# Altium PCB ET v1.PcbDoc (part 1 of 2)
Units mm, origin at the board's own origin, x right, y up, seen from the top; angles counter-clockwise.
Board outline 210 x 190 mm, 4 copper layers (Top Layer, GND, PWR, Bottom Layer), stack 0.538 mm thick; 137 components, 80 nets, 364 pads, 677 vias.
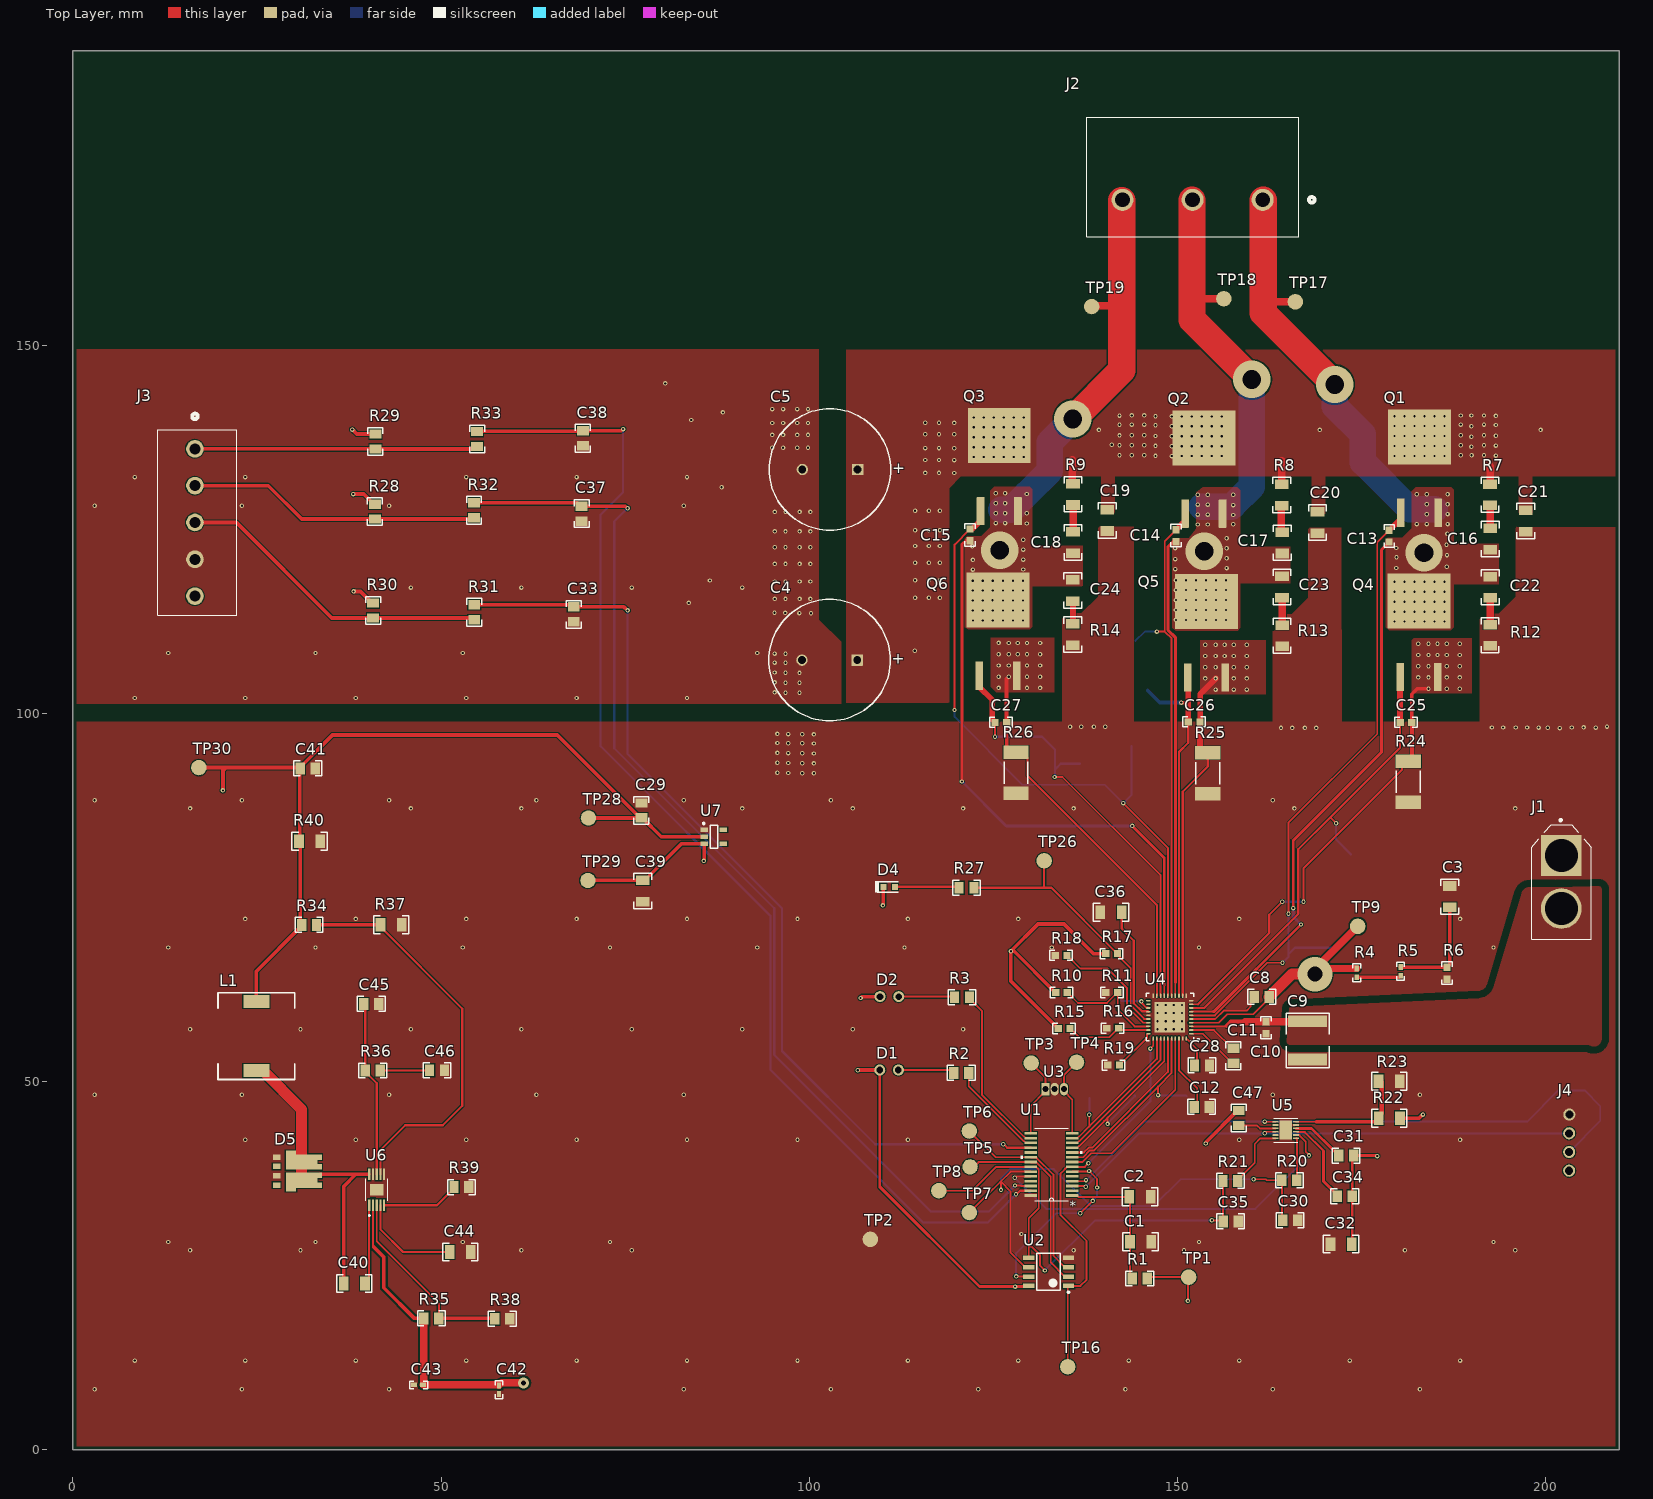
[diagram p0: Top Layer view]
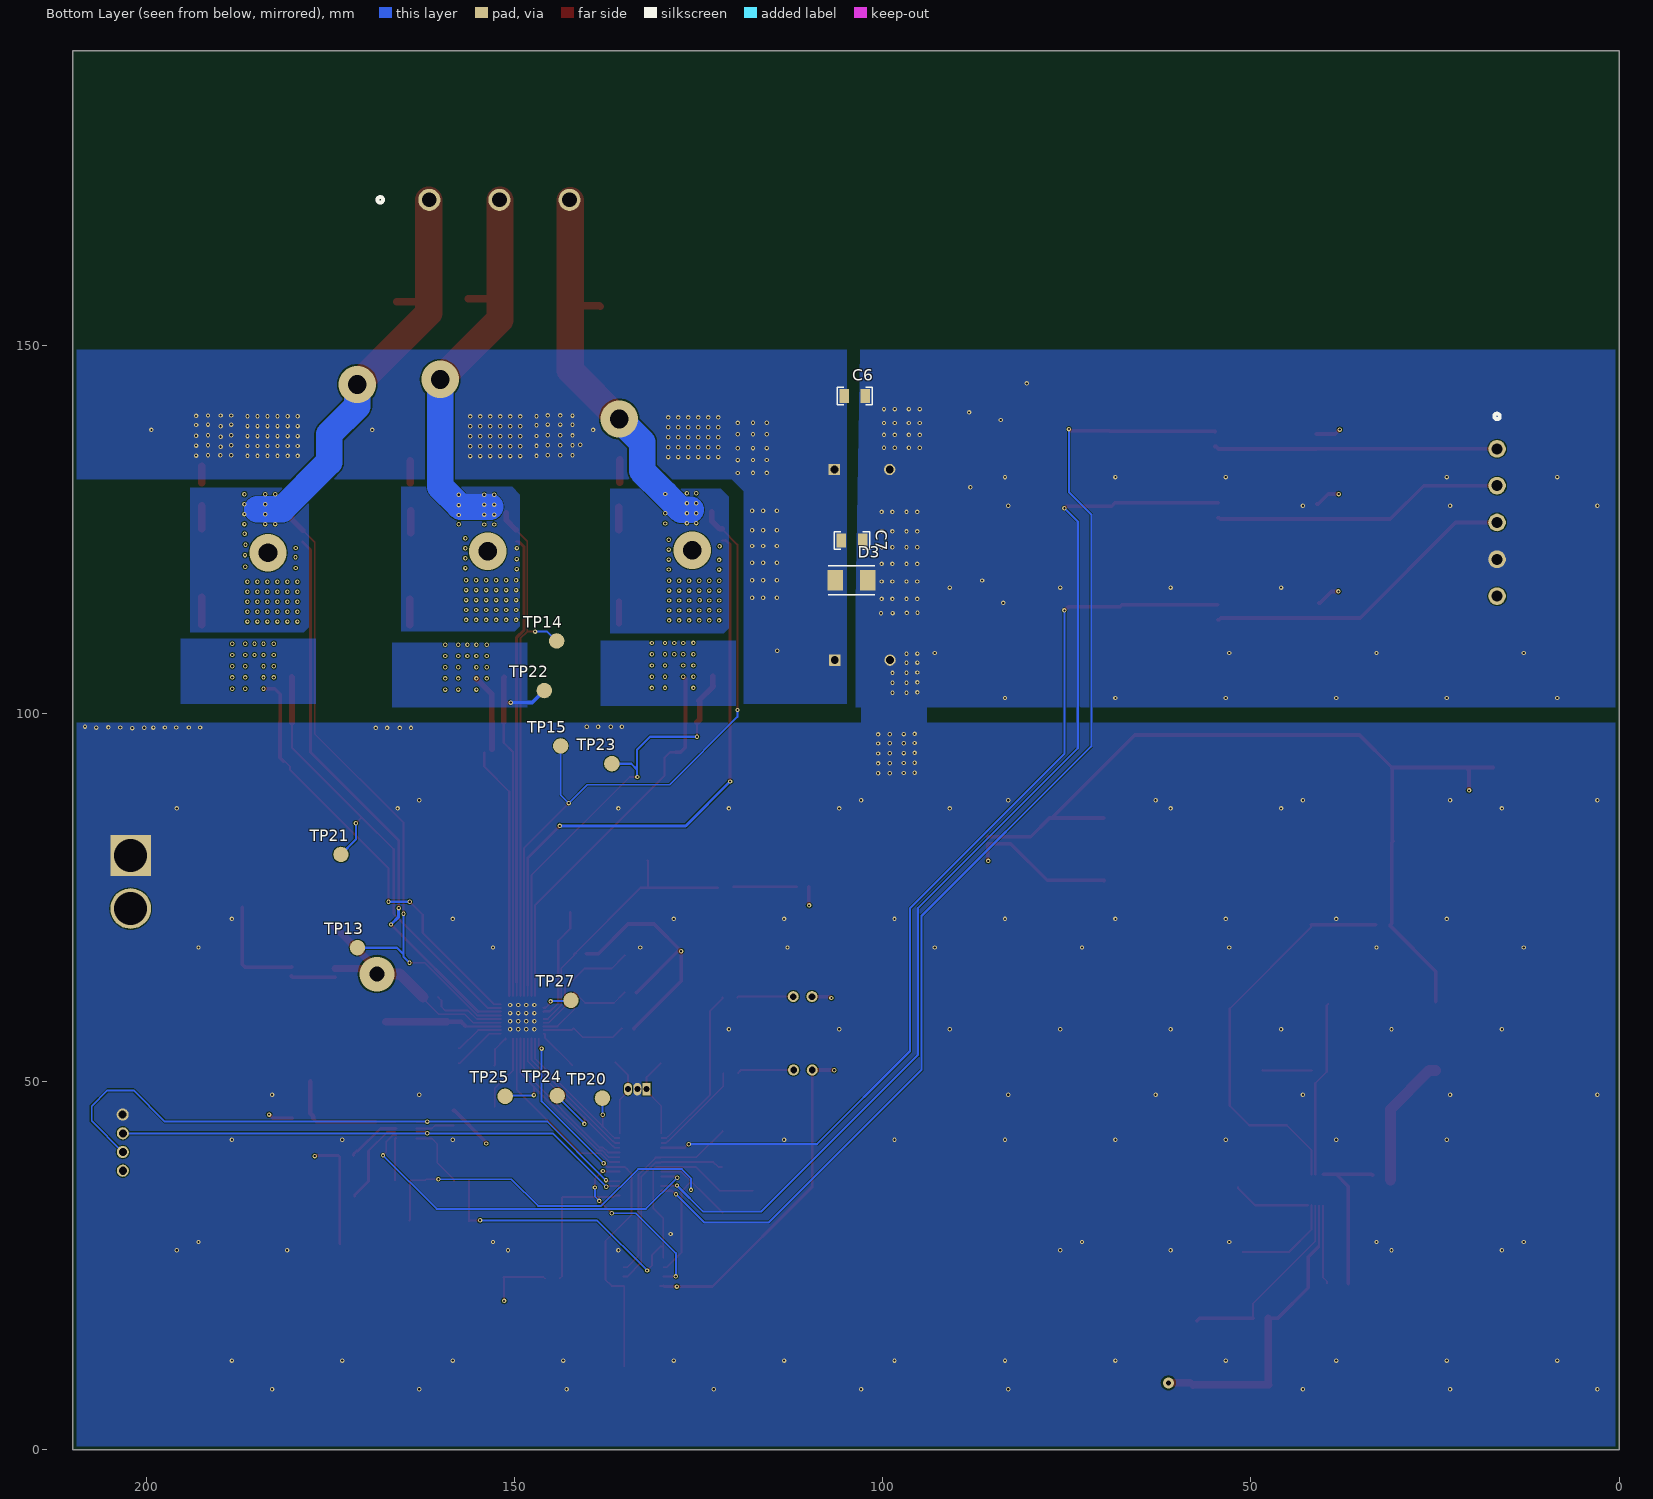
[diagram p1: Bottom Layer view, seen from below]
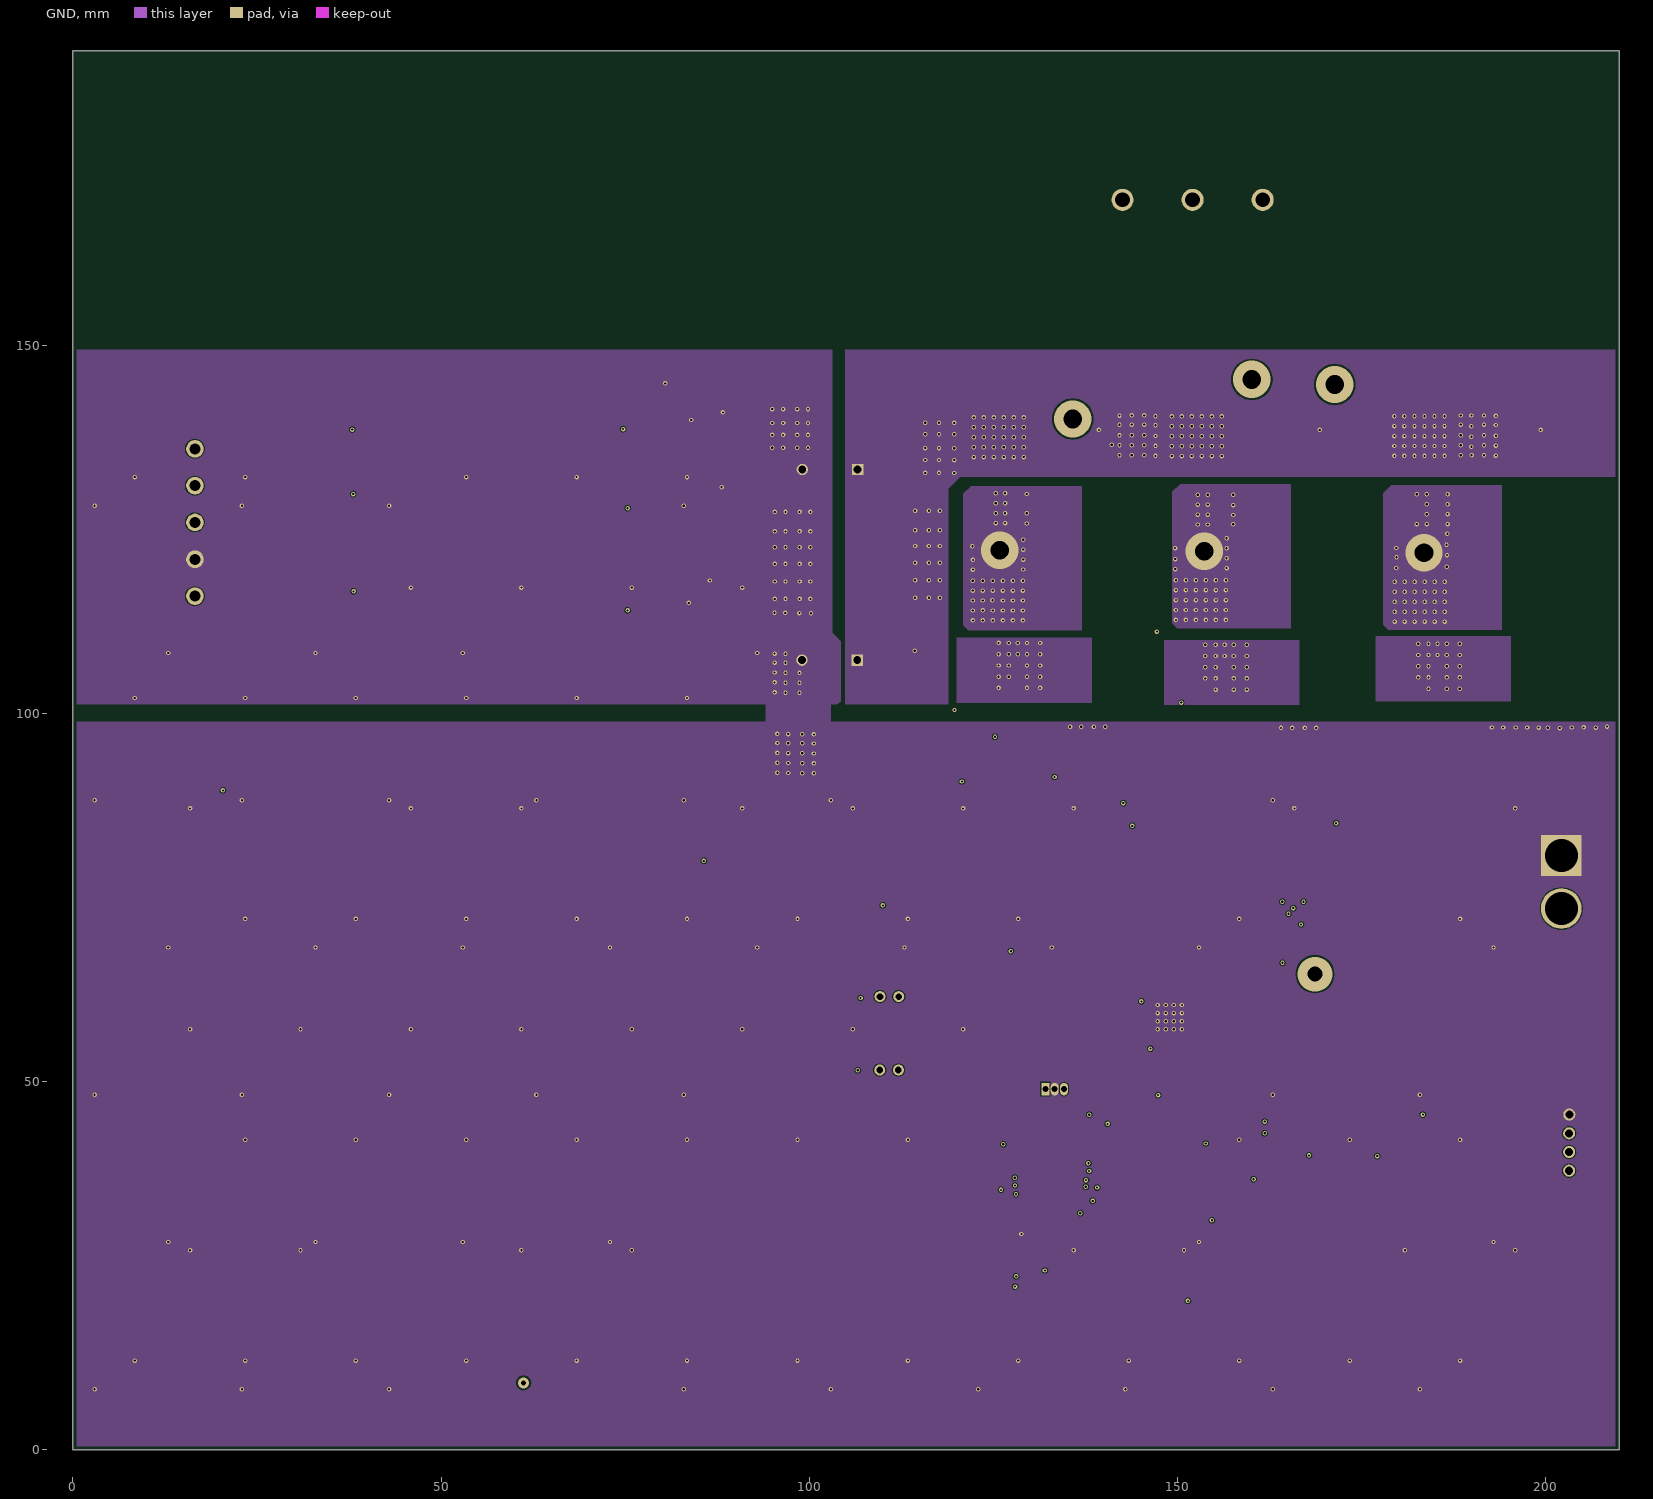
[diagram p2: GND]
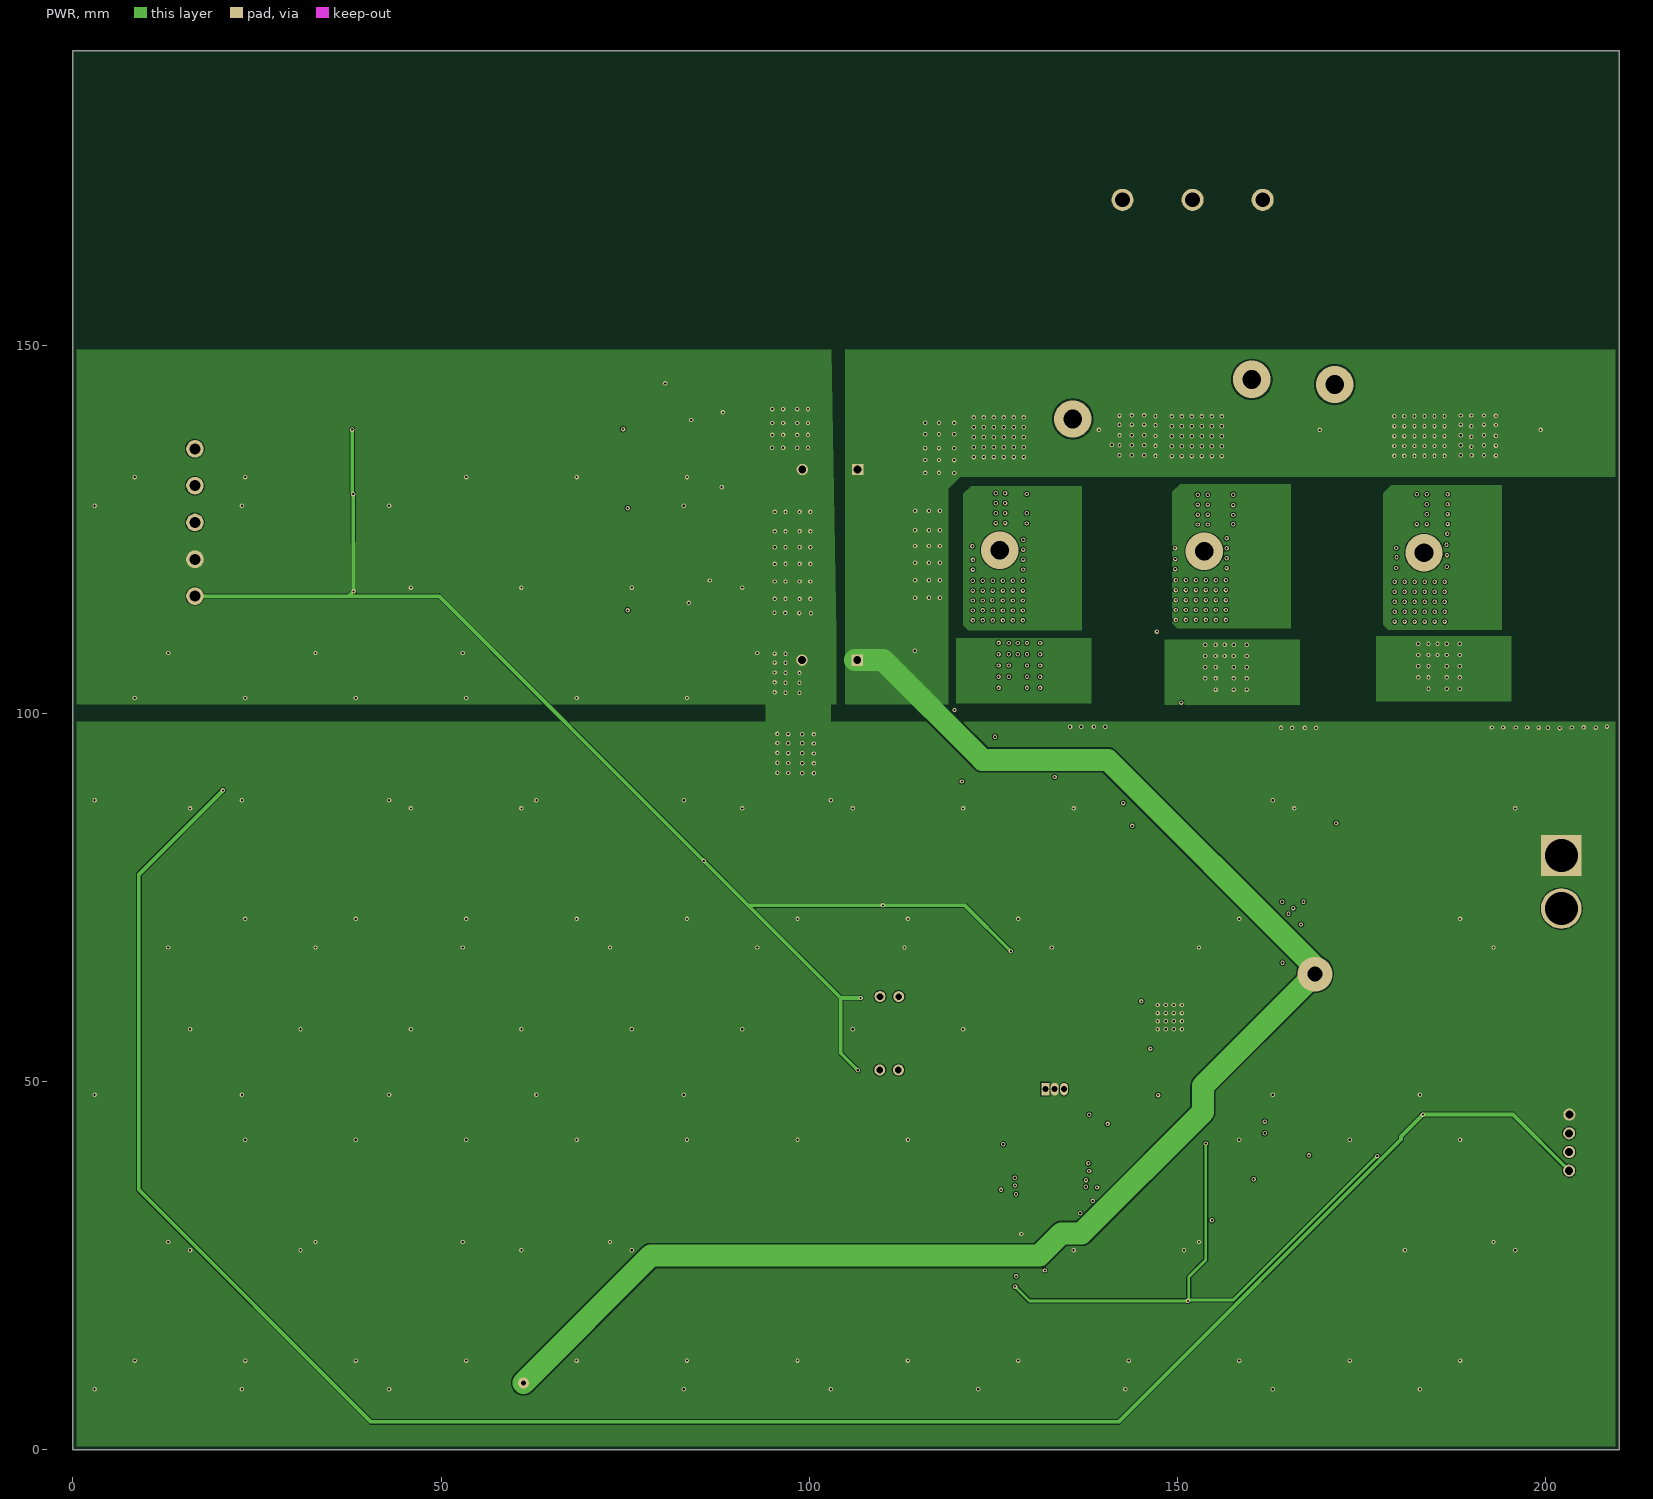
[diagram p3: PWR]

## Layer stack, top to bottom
Top Solder: solder mask 0.0102, Solder Resist, Dk 3.5
Top Layer: signal copper 0.0356
Dielectric 1: prepreg 0.0965, PP-012, Dk 4
GND: signal copper 0.0356
Dielectric3: core 0.2032, Core-024, Dk 4.6
PWR: signal copper 0.0356
Dielectric2: prepreg 0.0965, PP-012, Dk 4
Bottom Layer: signal copper 0.0356
Bottom Solder: solder mask 0.0102, Solder Resist, Dk 3.5

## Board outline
0,0 0,190 210,190 210,0

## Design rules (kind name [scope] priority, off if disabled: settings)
BoardOutlineClearance [All] p1: gap=0.5 ignorepadtopadclearanceinfootprint=FALSE
Clearance [//InNamedPolygon('Top_NetC13_1') &&  InNamedPolygon('NONET_L-01_P-001')] p1: gap=1 ignorepadtopadclearanceinfootprint=TRUE
Clearance "Board outline" [All vs InNet('VDC')] p2: gap=0.254 ignorepadtopadclearanceinfootprint=TRUE
Clearance Default [All] p3: gap=0.127 ignorepadtopadclearanceinfootprint=TRUE
ComponentClearance ComponentClearance_RS1 [InComponent('RS1') vs InComponent('L2')] p1: gap=0 collisioncheckmode=3 verticalgap=0 showdistances=FALSE
ComponentClearance ComponentClearance_J6 [InComponent('J6') vs InComponent('L4')] p2: gap=0 collisioncheckmode=3 verticalgap=0 showdistances=FALSE
ComponentClearance [All] p3: gap=0.25 collisioncheckmode=3 verticalgap=2540 showdistances=FALSE
DiffPairsRouting [InDifferentialPairClass('All Differential Pairs')] p1: maxlimit=0.254 minlimit=0.127 mostfreqgap=0.254 toplayer_maxgap=0.25 toplayer_prefgap=0.243 toplayer_minwidth=0.075 toplayer_maxwidth=0.25 toplayer_prefwidth=0.25 midlayer1_minwidth=0.381 midlayer1_maxwidth=0.381 midlayer1_prefwidth=0.381 midlayer2_minwidth=0.381 midlayer2_maxwidth=0.381 midlayer2_prefwidth=0.381 bottomlayer_maxgap=0.25 bottomlayer_prefgap=0.243 bottomlayer_minwidth=0.075 bottomlayer_maxwidth=0.25 bottomlayer_prefwidth=0.25 impedanceprofiledriven=TRUE maxuncoupledlength=12.7
Height [All] p1: minheight=0 maxheight=100 prefheight=12.7
HoleSize [All] p1: absolutevalues=TRUE maxlimit=10 minlimit=0.254 maxpercent=80.000 minpercent=20.000
HoleToHoleClearance [All] p1: gap=0.1 allowstackedmicrovias=TRUE
MatchedLengths [All] p1: tolerance=1 checknetsindiffpair=TRUE checkdiffpairvsdiffpair=FALSE checkxsignals=FALSE checkothers=FALSE
MinimumSolderMaskSliver [All] p1: minsoldermaskwidth=0.1
PasteMaskExpansion [All] p1: expansion=-0.1
PlaneClearance [All] p1: clearance=0.5
PolygonConnect [All] p1: connectstyle=Direct reliefconductorwidth=0.254 reliefentries=4 polygonreliefangle="90 Angle" airgapwidth=0.254
RoutingVias [All] p1: holewidth=0.254 width=0.508 viastyle="Through Hole" minholewidth=0.254 minwidth=0.508 maxholewidth=0.5 maxwidth=1
SilkToSilkClearance [All] p1 off: silktosilkclearance=0.254
SilkToSolderMaskClearance [IsPad] p1 off: minsilkscreentomaskgap=0.254 clearancetoexposedcopper=TRUE
SolderMaskExpansion [All] p1: expansion=0.05 istentingtop=FALSE
Width [All] p1: maxlimit=6.8 minlimit=0.127 preferedwidth=0.2 minimp=50.000000 maximp=50.000000 favimp=50.000000
20 further rules are at their usual default settings.

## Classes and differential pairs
component class "ETMicrocontroller Schematic": C1 C2 C30 C31 C32 C34 C35 C47 D1 D2 J4 R1 R2 R3 R20 R21 R22 R23 TP1 TP2 TP3 TP4 TP5 TP6 TP7 TP8 U1 U2 U3 U5
component class ET_SchDoc: C3 C4 C5 C6 C7 C8 C9 C10 C11 C12 C13 C14 C15 C16 C17 C18 C19 C20 C21 C22 C23 C24 C25 C26 C27 C28 C29 C33 C36 C37 C38 C39 C40 C41 C42 C43 C44 C45 C46 D3 D4 D5 "f x" J1 J2 J3 L1 Q1 Q2 Q3 Q4 Q5 Q6 R4 R5 R6 R7 R8 R9 R10 R11 R12 R13 R14 R15 R16 R17 R18 R19 R24 R25 R26 R27 R28 R29 R30 R31 R32 R33 R34 R35 R36 R37 R38 R39 R40 TP9 TP13 TP14 TP15 TP16 TP17 TP18 TP19 TP20 TP21 TP22 TP23 TP24 TP25 TP26 TP27 TP28 TP29 TP30 U4 U6 U7

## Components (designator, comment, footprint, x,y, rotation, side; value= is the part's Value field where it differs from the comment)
C1 "10uF" 1206 145.02,28.258 r0 top
C2 "0.1uF" 1206 144.942,34.362 r0 top
C3 "0.1uF" 1206 186.994,75.129 r270 top
C4 "390uF" YXJ_1600x2500 102.766,107.261 r180 top
C5 "390uF" YXJ_1600x2500 102.824,133.152 r180 top
C6 "2.2uF" 1206 103.814,143.137 r0 bottom
C7 "0.1uF" 1206 104.203,123.499 r0 bottom
C8 "1uF" 0805_HV 161.465,61.517 r180 top
C9 "10uF" 2220_280 167.71,55.6 r90 top
C10 "0.1uF" 0603 162.042,57.328 r90 top
C11 "0.047uF" 0805_HV 157.62,53.519 r90 top
C12 "1uF" 0805_HV 153.305,46.577 r180 top
C13 "1nF" 0603 178.779,124.093 r90 top
C14 "1nF" 0603 149.815,124.156 r90 top
C15 "1nF" 0603 121.837,124.26 r90 top
C16 "3900pF" 1206 192.494,123.694 r90 top
C17 "3900pF" 1206 164.236,123.191 r90 top
C18 "3900pF" 1206 135.834,123.242 r90 top
C19 "2.2uF" 1206 140.499,126.244 r90 top
C20 "2.2uF" 1206 169.035,125.949 r90 top
C21 "2.2uF" 1206 197.306,126.149 r90 top
C22 "3900pF" 1206 192.518,117.152 r90 top
C23 "3900pF" 1206 164.217,117.187 r90 top
C24 "3900pF" 1206 135.811,116.718 r90 top
C25 "1nF" 0603 181.064,98.809 r180 top
C26 "1nF" 0603 152.287,98.87 r0 top
C27 "1nF" 0603 126.033,98.801 r180 top
C28 "1uF" 0805_HV 153.348,52.211 r180 top
C29 "1uF" 0805_HV 77.207,86.843 r90 top
C30 "47pF" 0805_HV 165.322,31.167 r180 top
C31 "0.1uF" 0805_HV 172.932,39.968 r180 top
C32 "10uF" 1206 172.254,27.945 r0 top
C33 "1000pF" 0805_HV 68.008,113.473 r270 top
C34 "0.1uF" 0805_HV 172.742,34.438 r180 top
C35 "47pF" 0805_HV 157.238,31.014 r180 top
C36 "0.1uF" 1206 140.999,73.005 r0 top
C37 "1000pF" 0805_HV 69.087,127.158 r270 top
C38 "1000pF" 0805_HV 69.271,137.393 r270 top
C39 "2.2uF" 1206 77.404,75.906 r90 top
C40 "0.1uF" 1206 38.22,22.591 r180 top
C41 "47uF" 0805_HV 31.901,92.552 r180 top
C42 "2.2uF" 0402 57.87,8.157 r90 top
C43 "2.2uF" 0402 46.946,8.82 r0 top
C44 "0.1uF" 1206 52.609,26.869 r180 top
C45 "15pF" 0805_HV 40.519,60.565 r180 top
C46 "3300pF" 0805_HV 49.451,51.547 r180 top
C47 "0.1uF" 0805_HV 158.332,45.062 r90 top
D1 "LED" LED_TH 110.851,51.585 r0 top
D2 "LED" LED_TH 110.892,61.556 r0 top
D3 "SMBJ70CA-13-F" SMB-Bi 104.251,118.1 r0 bottom
D4 "RED" WL-SMCW_GREEN 110.871,76.463 r0 top
D5 "V8KM60DUHM3/H" V8KM60DUHM3/H 28.537,37.86 r270 top
J1 "XT60 PRT-10474" "XT60 PRT-10474" 202.16,77.116 r270 top
J2 "MotorPhase 1904150" "MotorPhase 1904150" 161.593,169.78 r180 top
J3 "MotorHall_1792892" MotorHall_1792892 16.571,135.953 r270 top
J4 "USB Header" "USB Header" 203.233,41.718 r90 top
L1 "27uH" MSS1038T-273MLC 24.917,56.197 r180 top
Q1 "CSD19536KTT" KTT0002A 182.886,134.169 r90 top
Q2 "CSD19536KTT" KTT0002A 153.601,134.045 r90 top
Q3 "CSD19536KTT" KTT0002A 125.814,134.388 r90 top
Q4 "CSD19536KTT" KTT0002A 182.824,111.885 r90 top
Q5 "CSD19536KTT" KTT0002A 153.967,111.813 r90 top
Q6 "CSD19536KTT" KTT0002A 125.65,112.04 r90 top
R1 "330" 0805_HV 144.89,23.271 r0 top
R2 "330" 0805_HV 120.657,51.198 r180 top
R3 "330" 0805_HV 120.754,61.468 r180 top
R4 "2.00M" 0402 174.381,64.779 r90 top
R5 "2.00M" 0402 180.32,64.988 r270 top
R6 "191k" 0603 186.635,64.737 r90 top
R7 "1.50" 1206 192.471,129.724 r90 top
R8 "1.50" 1206 164.185,129.688 r90 top
R9 "1.50" 1206 135.833,129.778 r90 top
R10 "75k" 0603 134.27,62.105 r180 top
R11 "75k" 0603 141.101,62.121 r0 top
R12 "1.50" 1206 192.482,110.632 r90 top
R13 "1.50" 1206 164.228,110.573 r90 top
R14 "1.50" 1206 135.813,110.725 r90 top
R15 "75k" 0603 134.623,57.229 r180 top
R16 "75k" 0603 141.224,57.258 r0 top
R17 "10k" 0603 141.082,67.391 r0 top
R18 "47k" 0603 134.209,67.164 r180 top
R19 "47k" 0603 141.34,52.234 r0 top
R20 "22" 0805_HV 165.222,36.606 r180 top
R21 "22" 0805_HV 157.214,36.523 r180 top
R22 "4.7k" 1206 178.795,45.039 r180 top
R23 "10k" 1206 178.776,50.074 r180 top
R24 "10m" 2512 181.391,90.738 r90 top
R25 "10m" 2512 154.143,91.899 r90 top
R26 "10m" 2512 128.087,91.964 r90 top
R27 "1k" 0805_HV 121.364,76.349 r0 top
R28 "3.3k" 0805_HV 41.022,127.436 r90 top
R29 "3.3k" 0805_HV 41.086,136.958 r90 top
R30 "3.3k" 0805_HV 40.774,114.005 r90 top
R31 "100" 0805_HV 54.515,113.77 r90 top
R32 "100" 0805_HV 54.473,127.603 r90 top
R33 "100" 0805_HV 54.884,137.286 r90 top
R34 "53.6k" 0805_HV 32.073,71.297 r180 top
R35 "113k" 0805_HV 48.68,17.852 r180 top
R36 "88.7k" 0805_HV 40.722,51.521 r180 top
R37 "10k" 1206 43.225,71.303 r180 top
R38 "5.49k" 0805_HV 58.312,17.796 r180 top
R39 "154k" 0805_HV 52.767,35.691 r180 top
R40 "10k" 1206 32.151,82.663 r180 top
TP1 "Test Point 1" TP200_SMD 151.539,23.453 r180 top
TP2 "Test Point 1" TP200_SMD 108.303,28.594 r90 top
TP3 "Test Point 1" TP200_SMD 130.156,52.531 r270 top
TP4 "Test Point 1" TP200_SMD 136.311,52.643 r270 top
TP5 "Test Point 1" TP200_SMD 121.849,38.424 r270 top
TP6 "Test Point 1" TP200_SMD 121.757,43.299 r270 top
TP7 "Test Point 1" TP200_SMD 121.75,32.222 r180 top
TP8 "Test Point 1" TP200_SMD 117.618,35.192 r180 top
TP9 "Test Point 1" TP200_SMD 174.503,71.105 r0 top
TP13 "Test Point 1" TP200_SMD 171.357,68.202 r90 bottom
TP14 "Test Point 1" TP200_SMD 144.301,109.862 r90 bottom
TP15 "Test Point 1" TP200_SMD 143.753,95.602 r90 bottom
TP16 "Test Point 1" TP200_SMD 135.118,11.28 r90 top
TP17 "Test Point 1" TP200_SMD 166.022,155.929 r270 top
TP18 "Test Point 1" TP200_SMD 156.312,156.34 r270 top
TP19 "Test Point 1" TP200_SMD 138.363,155.28 r270 top
TP20 "Test Point 1" TP200_SMD 138.083,47.769 r90 bottom
TP21 "Test Point 1" TP200_SMD 173.596,80.861 r90 bottom
TP22 "Test Point 1" TP200_SMD 145.97,103.128 r90 bottom
TP23 "Test Point 1" TP200_SMD 136.801,93.195 r90 bottom
TP24 "Test Point 1" TP200_SMD 144.218,48.095 r90 bottom
TP25 "Test Point 1" TP200_SMD 151.3,48.015 r90 bottom
TP26 "Test Point 1" TP200_SMD 131.914,80.007 r90 top
TP27 "Test Point 1" TP200_SMD 142.359,61.044 r90 bottom
TP28 "Test Point 1" TP200_SMD 70.022,85.813 r90 top
TP29 "Test Point 1" TP200_SMD 69.949,77.329 r90 top
TP30 "Test Point 1" TP200_SMD 17.11,92.665 r180 top
U1 "MSP430G2553IPW28" MSP430G2353IPW28 132.914,38.761 r180 top
U2 "MCP3202T-CI/SN" MCP3202T-CI/SN 132.518,24.164 r180 top
U3 "DRV5011" Hall_sensor 133.343,48.991 r0 top
U4 "DRV8353FHRTAR" DRV8353FHRTAR 148.975,58.763 r180 top
U5 "FT234XD-R" FT234XD-R 164.733,43.431 r180 top
U6 "TPS54160DGQ" TPS54160DGQ 41.258,35.317 r90 top
U7 "TPS709B345DBVR" TPS709B345DBVR 87.049,83.277 r0 top

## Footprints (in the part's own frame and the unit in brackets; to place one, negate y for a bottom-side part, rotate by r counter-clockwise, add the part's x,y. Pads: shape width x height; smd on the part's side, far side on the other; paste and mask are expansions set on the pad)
0402 [mm] "0402 from SM-752 data"
  rect 0.8x0.6 smd: 1(-0.6,0) 2(0.6,0)
  silkscreen extent -1.22,-0.52 1.22,0.52, body extent -0.55,-0.3 0.55,0.3, height 0.6
0603 [mm] "0603 from SM-752 data"
  rect 1x0.95 smd: 1(-0.8,0) 2(0.8,0)
  silkscreen extent -1.52,-0.69 1.52,0.69, body extent -0.87,-0.47 0.87,0.47, height 1
0805_HV [mil] "0805 with 30mil clearance between pads"
  rect 50x63 smd: 1(-40,0) 2(40,0)
  silkscreen extent -74,-40 74,40, body extent -43,-29 43,29, height 57
1206 [mm] "1206 from SM-752 data"
  rect 1.3x1.85 smd: 1(-1.45,0) 2(1.45,0)
  silkscreen extent -2.4,-1.21 2.4,1.21, body extent -1.7,-0.9 1.7,0.9, height 1.35
2220_280 [mm] "Chip Capacitor, Body 5.7x5.0mm, IPC Medium Density"
  rect 1.6x5.3 smd: 1(-2.6,0) 2(2.6,0)
  silkscreen extent -3.69,-2.94 3.69,2.94, body extent -2.95,-2.62 2.95,2.62, height 2.8
2512 [mm] "Chip Resistor, 2-Leads, Body 6.40x3.20mm, IPC Medium Density"
  rect 1.8x3.45 smd: 1(-2.775,0) 2(2.775,0)
  silkscreen extent -1.5,-1.63 1.5,1.63, body extent -3.32,-1.73 3.32,1.73, height 0.9
DRV8353FHRTAR [mm] "QFN, 40-Leads, Body 6.00x6.00mm, Pitch 0.50mm, Thermal Pad 4.15x4.15mm, IPC Medium Density"
  oval 0.6x0.22 smd: 1(-2.9,2.25) 2(-2.9,1.75) 3(-2.9,1.25) 4(-2.9,0.75) 5(-2.9,0.25) 6(-2.9,-0.25) 7(-2.9,-0.75) 8(-2.9,-1.25) 9(-2.9,-1.75) 10(-2.9,-2.25) 21(2.9,-2.25) 22(2.9,-1.75) 23(2.9,-1.25) 24(2.9,-0.75) 25(2.9,-0.25) 26(2.9,0.25) 27(2.9,0.75) 28(2.9,1.25) 29(2.9,1.75) 30(2.9,2.25)
  oval 0.22x0.6 smd: 11(-2.25,-2.9) 12(-1.75,-2.9) 13(-1.25,-2.9) 14(-0.75,-2.9) 15(-0.25,-2.9) 16(0.25,-2.9) 17(0.75,-2.9) 18(1.25,-2.9) 19(1.75,-2.9) 20(2.25,-2.9) 31(2.25,2.9) 32(1.75,2.9) 33(1.25,2.9) 34(0.75,2.9) 35(0.25,2.9) 36(-0.25,2.9) 37(-0.75,2.9) 38(-1.25,2.9) 39(-1.75,2.9) 40(-2.25,2.9)
  rect 4.15x4.15 smd: 41(0,0)
  silkscreen extent -4,-3.22 3.22,3.22, body extent -3.08,-3.08 3.08,3.08, height 0.8
FT234XD-R [mil]
  rect 32x9 smd paste+0 mask+0: 1(-55,44.29) 2(-55,26.57) 3(-55,8.86) 4(-55,-8.86) 5(-55,-26.57) 6(-55,-44.29) 7(55,-44.29) 8(55,-26.57) 9(55,-8.86) 10(55,8.86) 11(55,26.57) 12(55,44.29)
  rect 65x100 smd paste+0 mask+0: 13(0,0)
  silkscreen extent -64,-64 64,64, body extent -59,-59 59,59, height 32
Hall_sensor [mm]
  rect 1.07x1.7 hole 0.813 mask+0: 1(-1.27,0)
  oval 1.07x1.7 hole 0.813 mask+0: 2(0,0) 3(1.27,0)
KTT0002A [mm] "TO-263-2"
  rrect10% 3.82x1.05 smd: 1(-6.9,2.54) 3(-6.9,-2.54)
  rrect1% 7.48x8.55 smd paste-4.2: 2(3.4,0)
  body extent -8.03,-5.08 7.05,5.08, height 4.67
LED_TH [mm]
  round 1.5 hole 0.9 mask+0: 1(-1.27,0) 2(1.27,0)
MCP3202T-CI/SN [mm] "SOIC, 8-Leads, Body 4.90x3.90mm, Pitch 1.27mm, IPC Medium Density"
  rect 1.55x0.6 smd: 1(-2.7,1.905) 2(-2.7,0.635) 3(-2.7,-0.635) 4(-2.7,-1.905) 5(2.7,-1.905) 6(2.7,-0.635) 7(2.7,0.635) 8(2.7,1.905)
  silkscreen extent -2.83,-2.5 1.6,2.88, body extent -2,-2.5 2,2.5, height 1.75
MotorHall_1792892 [mm]
  round 2.4 hole 1.5 mask+0: 1(0,0) 2(5,0) 3(10,0) 4(15,0) 5(20,0)
  silkscreen extent -4.79,-5.08 22.63,5.68, body extent 0,0 0.25,0.25, height 0.25
"MotorPhase 1904150" [mm]
  round 3 hole 2 mask+0: 1(0,0) 2(9.52,0) 3(19.04,0)
  silkscreen extent -7.05,-11.23 23.93,5.03, body extent 0,0 0.25,0.25, height 0.25
MSP430G2353IPW28 [mil]
  rect 66x14 smd: 1(-111,166.34) 2(-111,140.75) 3(-111,115.16) 4(-111,89.57) 5(-111,63.98) 6(-111,38.39) 7(-111,12.8) 8(-111,-12.8) 9(-111,-38.39) 10(-111,-63.98) 11(-111,-89.57) 12(-111,-115.16) 13(-111,-140.75) 14(-111,-166.34) 15(111,-166.34) 16(111,-140.75) 17(111,-115.16) 18(111,-89.57) 19(111,-63.98) 20(111,-38.39) 21(111,-12.8) 22(111,12.8) 23(111,38.39) 24(111,63.98) 25(111,89.57) 26(111,115.16) 27(111,140.75) 28(111,166.34)
  silkscreen extent -164,-193 164,193, body extent -130,-193 130,193, height 47
MSS1038T-273MLC [mil] "Coilcraft Shielded Power Inductors"
  rect 140x70 smd: 1(0,185) 2(0,-185)
  silkscreen extent -205,-232 205,232, body extent -201,-203 201,203, height 158
SMB-Bi [mm] "Molded Diode, 2-Leads, Body 5.4x3.6mm, IPC Medium Density, based on OnSemi component dimensions"
  rect 2.159x2.743 smd: 1(-2.21,0) 2(2.21,0)
  silkscreen extent -3.17,-1.99 3.17,1.99, body extent -2.65,-1.85 2.65,1.85, height 2.26
TP200_SMD [mm] "Test Point, Single Side Land,2.00mm Land SMD"
  round 2.1 smd paste-10 mask-0.1: 1(0,0)
  body extent -0.99,-1 1,1, height 0.02
TPS709B345DBVR [mm] "SOT23, 5-Leads, Body 2.90x2.80mm, Pitch 0.95mm, IPC Medium Density"
  rect 1x0.6 smd: 1(-1.3,0.95) 2(-1.3,0) 3(-1.3,-0.95) 4(1.3,-0.95) 5(1.3,0.95)
  silkscreen extent -1.5,-1.55 0.5,1.92, body extent -1.5,-1.53 1.5,1.53, height 1.45
TPS54160DGQ [mm]
  rect 1.6x0.3 smd paste-2 mask+0: 1(-2.1,1) 2(-2.1,0.5) 3(-2.1,0) 4(-2.1,-0.5) 5(-2.1,-1) 6(2.1,-1) 7(2.1,-0.5) 8(2.1,0) 9(2.1,0.5) 10(2.1,1)
  rect 1.57x1.88 smd: 11(0,0)
  silkscreen extent -3.6,-1.5 1.5,1.5, body extent -2.45,-1.5 2.45,1.5, height 1.1
"USB Header" [mil] "1x4 Header, Through Hole, Vertical"
  round 65 hole 43.3 mask+2.95: 1(-150,0.5) 2(-50,0.5) 3(50,0.5) 4(150.01,-0.5)
  body extent -200,-50 200,50, height 341
V8KM60DUHM3/H [mm]
  rect 0.75x1 smd: 1(-1.905,-0.875) 2(-0.635,-0.875) 3(0.635,-0.875) 4(1.905,-0.875)
  rect 0.5x1.4 smd: 5(-2.514,1.073) 7(2.52,1.074)
  rect 0.75x0.65 smd: 5(-1.905,4.95) 6(-0.574,4.95) 7(0.577,4.95) 8(1.905,4.953)
  rect 2.08x4.28 smd: 5(-1.24,2.515) 7(1.24,2.515)
WL-SMCW_GREEN [mm] "WURTH"
  rect 0.8x0.8 smd: 1(-0.8,0) 2(0.8,0)
  silkscreen extent -1.9,-0.8 1.2,0.8, body extent -0.85,-0.45 0.85,0.45, height 0.8
"XT60 PRT-10474" [mm]
  rect 5.516x5.516 hole 4.5: 1(-3.6,0)
  round 5.516 hole 4.5: 2(3.6,0)
  silkscreen extent -8.55,-4.05 7.75,4.05
YXJ_1600x2500 [mm] "TH, 2-Leads, Dia 16mm, Pin Spacing 7.5mm"
  rrect6% 1.55x1.55 hole 1.05: 1(-3.75,0)
  round 1.55 hole 1.05: 2(3.75,0)
  silkscreen extent -8.25,-8.25 8.25,8.25, body extent -8.25,-8.25 8.26,8.25, height 27.01

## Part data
C1 C32: library part C_10uF_CL31B106KOHVPJE, "MLCC10UF16V 10 X7R1206", Case Code (Imperial)=1206, Case Code (Metric)=3216, Dielectric=X7R, Dielectric Material=Ceramic, Manufacturer=TDK, Manufacturer Part Number=C3216X7R1V106M160AC, Max Operating Temperature=125°C, Min Operating Temperature=-55°C, Package Quantity=2000, Tolerance=20%, Voltage Rating=35V
C2 C36 C40 C44: library part "C_0.1uF 885012206020 CAP CER 0.1UF 10V X7R 0603", "CAP CER 0.1UF 10V X7R 0603", Capacitance=100nF, Case Code (Imperial)=1206, Case Code (Metric)=3216, Dielectric=X7R, Manufacturer=TDK, Manufacturer Part Number=C3216X7R2A104K160AA, Max Operating Temperature=125°C, Min Operating Temperature=-55°C, Package Quantity=2000, Resistor Type=Ceramic, Supplier Part Number 1=445-1377-1-ND, Tolerance=10%, Voltage=100V
C3: library part "C_0.1uF 885012208009", "CAP CER 0.1UF 10V X7R 1206", Part Number=885012208009
C4 C5: library part "C_390uF EEU-FS2A391", "CAP ALUM 390UF 20% 100V THRUHOLE", Manufacturer=Panasonic, Manufacturer Part Number=EEU-FS2A391, Supplier Part Number 1=1763833
C6 C19 C20 C21 C39: library part "C_2.2uF CL31B225KCHSNNE", "Cap Ceramic 2.2uF 100V X7R 10% Pad SMD 1206 Soft Termination 125C T/R", Case Code (Imperial)=1206, Case Code (Metric)=3216, Manufacturer=Samsung, Manufacturer Part Number=CL31B225KCHSNNE, Max Operating Temperature=125°C, Min Operating Temperature=-55°C, Supplier Part Number 1=5050148, Tolerance=10%, Voltage Rating=100V
C7: library part "C_0.1uF C3216X7R2A104K160AA", "CAP CER 0.1UF 100V X7R 1206", Capacitance=100nF, Case Code (Imperial)=1206, Case Code (Metric)=3216, Dielectric=X7R, Manufacturer=TDK, Manufacturer Part Number=C3216X7R2A104K160AA, Max Operating Temperature=125°C, Min Operating Temperature=-55°C, Package Quantity=2000, Resistor Type=Ceramic, Supplier Part Number 1=445-1377-1-ND, Tolerance=10%, Voltage=100V
C8 C28 C29: library part "C_1uF CGA4J2X5R1C105M125AA", "1 µF ±20% 16V Ceramic Capacitor X5R 0805 (2012 Metric)", Part Number=CGA4J2X5R1C105M125AA
C9: library part "C_10uF 22201C106MAT2A", "Cap Ceramic 10uF 100V X7R 20% SMD 2220 125°C Embossed T/R", Case Code (Imperial)=2220, Case Code (Metric)=5750, Dielectric=X7R, Manufacturer="Kyocera AVX", Manufacturer Part Number=22201C106MAT2A, Max Input Voltage=60V, Max Operating Temperature=125°C, Max Output Current=1.5A, Max Output Voltage=58V, Min Input Voltage=3.5V, Min Operating Temperature=-55°C, Min Output Voltage=800mV, Package Quantity=80, Quiescent Current=116uA, Supplier Part Number 1=478-9622-1-ND, Switching Frequency=581kHz, Tolerance=20%, Voltage Rating=100V
C10: library part "C_0.1uF GRM188R72A104KA35D", "0603 0.1 uF 100 V ±10 % Tolerance X7R SMT Multilayer Ceramic Capacitor", Capacitance=100nF, Case Code (Imperial)=0603, Case Code (Metric)=1608, Dielectric=X7R, Manufacturer=Murata, Manufacturer Part Number=GRM188R72A104KA35D, Max Operating Temperature=125°C, Min Operating Temperature=-55°C, Package Quantity=1, Supplier Part Number 1=03AC2685, Tolerance=10%, Voltage=100V
C11: library part "C_0.047uF GRM21BR72A473KA01L", "Cap Ceramic 0.047uF 100V X7R 10% SMD 0805 125C Embossed T/R", Capacitance=47nF, Case Code (Imperial)=0805, Case Code (Metric)=2012, Dielectric=X7R, Manufacturer=Murata, Manufacturer Part Number=GRM21BR72A473KA01L, Max Operating Temperature=125°C, Min Operating Temperature=-55°C, Package Quantity=3000, Supplier Part Number 1=7045792, Tolerance=10%, Voltage=100V
C12: library part "C_1uF LGC26D105MAT2S1", "CAP CER 1UF 6.3V X5R 0805", Part Number=LGC26D105MAT2S1
C13 C14 C15 C25 C26 C27: library part "C_1nF 885012206083", "CAP, CERM, 1000 pF, 50 V,+/- 10%, X7R, 0603", Supplier Part Number 1=885012206083
C16 C17 C18 C22 C23 C24: library part "C_3900pF 12061C392KAZ2A", "CAP CER 3900PF 100V X7R 1206", Supplier Part Number 1=09R8320
C30 C35: library part C_47pF_C0805C470K5RAC7800, "CAP CER 47PF 50V X7R 0805", Capacitance=1uF, Case Code (Imperial)=0402, Case Code (Metric)=1005, Manufacturer=Samsung, Manufacturer Part Number=CL05A105MO5NNNC, Max Operating Temperature=85°C, Min Operating Temperature=-55°C, Package Quantity=10000, Supplier Part Number 1=9107485, Tolerance=20%, Voltage Rating=16V
C31 C34: library part C_0.1uF_C0805C104K6RAC7800, "CAP CER SMD 0805 .1UF 35V 10% X7", Capacitance=2.2uF, Case Code (Imperial)=0402, Case Code (Metric)=1005, Manufacturer="Wurth Electronics", Manufacturer Part Number=885012105013, Max Operating Temperature=85°C, Min Operating Temperature=-55°C, Supplier Part Number 1=732-7490-1-ND, Tolerance=20%, Voltage Rating=10V
C33 C37 C38: library part "C_1000pF CC0805JRNPO9BN102", "Capacitor 1NF 50V 0805 SMD Npo (reel)", Capacitance=1nF, Case Code (Imperial)=0805, Case Code (Metric)=2012, Dielectric=C0G, Dielectric Material=Ceramic, Insulation Resistance=10GR, Manufacturer=Yageo, Manufacturer Part Number=CC0805JRNPO9BN102, Max Operating Temperature=125°C, Min Operating Temperature=-55°C, Package Quantity=4000, Supplier Part Number 1=311-1122-1-ND, Temperature Coefficient=30ppm/°C, Tolerance=5%, Voltage=50V
C41: library part "C_47uF C0805C476M9PACTU", "Cap Ceramic 47uF 6.3V X5R 20% SMD 0805 Plastic T/R", Case Code (Imperial)=0805, Case Code (Metric)=2012, Dielectric=X5R, Dielectric Material=Ceramic, Manufacturer=KEMET, Manufacturer Part Number=C0805C476M9PACTU, Max Operating Temperature=85°C, Min Operating Temperature=-55°C, Package Quantity=3000, Supplier Part Number 1=399-5506-1-ND, Tolerance=20%, Voltage=6.3V
C42 C43: library part "C_2.2uF 885012105013", "Cap, 2.2UF, 10V, 20%, X5R, 0402", Case Code (Imperial)=0402, Case Code (Metric)=1005, Manufacturer="Wurth Electronics", Manufacturer Part Number=885012105013, Max Operating Temperature=85°C, Min Operating Temperature=-55°C, Supplier Part Number 1=732-7490-1-ND, Tolerance=20%, Voltage Rating=10V
C45: library part "C_15pF 08055A150GAT2A", "Capacitor, ceramic, 15Pf, 50Vdc, 2-% Tol, 2+% Tol, c0G-Tc Code, -30, 30Ppm-Tc Rohs Compliant: Yes", Case Code (Imperial)=0805, Case Code (Metric)=2012, Dielectric=C0G, Manufacturer="Kyocera AVX", Manufacturer Part Number=08055A150GAT2A, Max Operating Temperature=125°C, Min Operating Temperature=-55°C, Package Quantity=4000, Supplier Part Number 1=478-11884-1-ND, Tolerance=2%, Voltage Rating=50V
C46: library part "C_3300pF 885012207119", "Cap, 3300PF, 100V, 10%, X7R, 0805", Capacitance=3.3nF, Case Code (Imperial)=0805, Case Code (Metric)=2012, Manufacturer="Wurth Electronics", Manufacturer Part Number=885012207119, Max Operating Temperature=125°C, Min Operating Temperature=-55°C, Supplier Part Number 1=732-12059-1-ND, Tolerance=10%, Voltage Rating=100V
C47: library part C_0.1uF_C0805C104K6RAC7800, "CAP CER SMD 0805 .1UF 35V 10% X7"
D3: library part "Diode SMBJ70CA-13-F", "Diode TVS Single Bi-Dir 70V 600W 2-Pin SMB T/R", Breakdown Voltage=89.5V, Case/Package=SMB, Clamping Voltage=113V, Leakage Current=400uA, Manufacturer=Diodes, Manufacturer Part Number=SMBJ7.0CA-13-F, Max Operating Temperature=150°C, Max Power Dissipation=600W, Max Reverse Leakage Current=5uA, Max Surge Current=5.3A, Min Breakdown Voltage=77.8V, Min Operating Temperature=-55°C, Package Body Material=Plastic, Package Quantity=1, Package Shape=Rectangular, Peak Reflow Temperature (Cel)=245°C, Power Line Protection=No, Resistor Type=Zener, Reverse Breakdown Voltage=7.78V, Reverse Standoff Voltage=70V, Supplier Part Number 1=7749799, Test Current=1mA, Time @ Peak Reflow Temperature-Max (s)=5s, Voltage Rating (DC)=7V
D4: library part "LED_Red 150060RS75000", "LED Low-Power Uni-Color Red 630nm 2V 2-Pin Chip 0603(1608Metric) T/R", Case Code (Imperial)=0603, Case Code (Metric)=1608, Color=Red, Forward Current=30mA, Forward Voltage=2V, Manufacturer="Wurth Electronics", Manufacturer Part Number=150060RS75000, Max Operating Temperature=85°C, Min Operating Temperature=-40°C, Package Quantity=1, Supplier Part Number 1=732-4978-1-ND, Test Current=20mA
D5: library part "Diode V8KM60DUHM3/H", "Diode Array 2 Independent Schottky 60 V 8A Surface Mount 8-PowerTDFN"
J1: "XT60 Connectors Male/female Pair", Manufacturer=SparkFun, Manufacturer Part Number=PRT-10474, Supplier Part Number 1=1568-1816-ND
J2: "Conn PC Terminal Block 3 POS 9.52mm Solder ST Thru-Hole 32A", Color=Green, Current=30A, Current Rating=32A, Flammability Rating="UL94 V-0", Manufacturer="Phoenix Contact", Manufacturer Part Number=1904150, Max Supply Voltage=800V, Package Quantity=50, Supplier Part Number 1=277-6184-ND, Voltage=600V, Voltage Rating=1kV
J3: "Wire-To-Board Terminal Block, 5, 400 V, 12 A, 26 Awg, 14 Awg, 2.5 Mm Rohs Compliant: Yes", Color=Green, Current=10A, Manufacturer="Phoenix Contact", Manufacturer Part Number=1792892, Package Quantity=100, Supplier Part Number 1=78T0423, Voltage=300V
J4: "2.54mm pitch, 1mm hole", Color=Green, Current=30A, Current Rating=32A, Flammability Rating="UL94 V-0", Manufacturer="Phoenix Contact", Manufacturer Part Number=1904150, Max Supply Voltage=800V, Package Quantity=50, Voltage=600V, Voltage Rating=1kV
L1: library part "L_27uH MSS1038T-273MLC", "Power inductor, shielded, 10/20/30% tol, SMT, RoHS", Case/Package=SMD/SMT, DC Resistance (DCR)=89mR, Inductance Tolerance=20%, Manufacturer=Coilcraft, Manufacturer Part Number=MSS1038T-273MLC, Max DC Current=2.35A, Max Operating Temperature=125°C, Min Operating Temperature=-40°C, Package Quantity=250, Saturation Current=1.98A, Self Resonant Frequency=15MHz, Supplier Part Number 1=994-MSS1038T-273MLC, Test Frequency=100kHz
Q1 Q2 Q3 Q4 Q5 Q6: library part "MOSFET CSD19536KTT", "This 100 V, 2.0 m D2PAK (TO-263) NexFET power MOSFET is designed to minimize losses in power conversion applications.", Case/Package=D2PAK, Continuous Drain Current (ID)=200A, Drain to Source Voltage (Vdss)=100V, Gate to Source Voltage (Vgs)=20V, Input Capacitance=12nF, Manufacturer="Texas Instruments", Max Operating Temperature=175°C, Max Power Dissipation=375W, Min Operating Temperature=-55°C
R1 R2 R3: library part "R_ 330_ERJ-P6WJ331V", "330 Ohms ±1% 0.5W, 1/2W Chip Resistor 0805 (2012 Metric) Automotive AEC-Q200, Pulse Withstanding Thick Film"
R4 R5: library part "R_2M CRCW04022M00FKED", "Res Thick Film 0402 2M Ohm 1% 1/16W ±100ppm/°C Molded SMD SMD Paper T/R", Case Code (Imperial)=0402, Case Code (Metric)=1005, Manufacturer=Vishay, Manufacturer Part Number=CRCW04022M00FKED, Max Operating Temperature=155°C, Max Power Dissipation=63mW, Min Operating Temperature=-55°C, Package Quantity=10, Resistance=2MR, Resistance Tolerance=1%, Resistor Type="Thick Film", Supplier Part Number 1=6789125P, Temperature Coefficient=100ppm/°C, Voltage Rating=50V
R6: library part "R_191k RC0603FR-07191KL", "RES 191K OHM 1% 1/10W 0603", Part Number=RC0603FR-07191KL
R7 R8 R9 R12 R13 R14: library part "R_1.50 CRCW12061R50FKEA", "Thick Film Resistors - SMD 1/4watt 1.5ohms 1%", Case Code (Imperial)=1206, Case Code (Metric)=3216, Manufacturer="Vishay Dale", Manufacturer Part Number=CRCW12061R50FKEA, Max Operating Temperature=155°C, Max Power Dissipation=250mW, Min Operating Temperature=-55°C, Package Quantity=10, Resistance=1.5R, Resistance Tolerance=1%, Resistor Type="Thick Film", Temperature Coefficient=100ppm/°C, Voltage Rating=200V
R10 R11 R15 R16: library part "R_75k CRCW060375K0JNEA", "Res Thick Film 0603 75K Ohm 5% 1/10W ±200ppm/°C Molded SMD SMD Paper T/R", Case Code (Imperial)=0603, Case Code (Metric)=1608, Manufacturer="Vishay Dale", Manufacturer Part Number=CRCW060375K0JNEA, Max Operating Temperature=155°C, Max Power Dissipation=100mW, Min Operating Temperature=-55°C, Package Quantity=1, Resistance=75kR, Resistance Tolerance=5%, Resistor Type="Thick Film", Supplier Part Number 1=84AH5250, Temperature Coefficient=200ppm/°C, Voltage Rating=75V
R17: library part "R_10k RC0603FR-0710KL", "RES 10K OHM 1% 1/10W 0603", Part Number=RC0603FR-0710KL
R18 R19: library part "R_47k CRCW060347K0JNEA", "Res Thick Film 0603 47K Ohm 5% 1/10W ±200ppm/°C Molded SMD SMD Paper T/R", Case Code (Imperial)=0603, Case Code (Metric)=1608, Manufacturer=Vishay, Manufacturer Part Number=CRCW060347K0JNEA, Max Operating Temperature=155°C, Max Power Dissipation=100mW, Min Operating Temperature=-55°C, Package Quantity=1, Resistance=47kR, Resistance Tolerance=5%, Resistor Type="Thick Film", Supplier Part Number 1=59M6815, Temperature Coefficient=200ppm/°C, Voltage Rating=75V
R20 R21: library part R_22_ERJ-P06F22R0V, "RES SMD 22 OHM 1% 1/2W 0805", Case Code (Imperial)=0603, Case Code (Metric)=1608, Manufacturer=Vishay, Manufacturer Part Number=CRCW060347K0JNEA, Max Operating Temperature=155°C, Max Power Dissipation=100mW, Min Operating Temperature=-55°C, Package Quantity=1, Resistance=47kR, Resistance Tolerance=5%, Resistor Type="Thick Film", Supplier Part Number 1=59M6815, Temperature Coefficient=200ppm/°C, Voltage Rating=75V
R22: library part "R_4.7k CRGP1206F4K7", "RES 4.7K OHM 1% 1/2W 1206", Case Code (Imperial)=0402, Case Code (Metric)=1005, Manufacturer=Panasonic, Manufacturer Part Number=ERJ-2RKF1002X, Max Operating Temperature=155°C, Max Power Dissipation=100mW, Min Operating Temperature=-55°C, Package Quantity=1, Resistance=10kR, Resistor Type="Thick Film", Supplier Part Number 1=85Y8053, Temperature Coefficient=100ppm/°C, Tolerance=1%, Voltage Rating=50V
R23 R37 R40: library part R_10k_RE1206FRE0710KL, "RES SMD 10K OHM 1% 1/4W 1206", Case Code (Imperial)=0603, Case Code (Metric)=1608, Manufacturer=Vishay, Manufacturer Part Number=CRCW060347K0JNEA, Max Operating Temperature=155°C, Max Power Dissipation=100mW, Min Operating Temperature=-55°C, Package Quantity=1, Resistance=47kR, Resistance Tolerance=5%, Resistor Type="Thick Film", Supplier Part Number 1=59M6815, Temperature Coefficient=200ppm/°C, Voltage Rating=75V
R24 R25 R26: library part "R_10m CSR2512A0R01F", "Res 2512 0.01 Ohm 1% 2W ±50/±75ppm/C Pad SMD T/R", Case Code (Imperial)=2512, Case Code (Metric)=6432, Manufacturer=Riedon, Manufacturer Part Number=CSR2512A0R01F, Max Operating Temperature=170°C, Max Power Dissipation=2W, Min Operating Temperature=-55°C, Package Quantity=2000, Resistance=10mR, Resistor Type="Metal Element", Supplier Part Number 1=696-1180-1-ND, Temperature Coefficient=50ppm/°C, Tolerance=1%
R27: library part "R_1k CR0805-FX-1001ELF", "Res Thick Film 0805 1K Ohm 1% 1/8W ±100ppm/°C Molded SMD SMD Paper Tape on Plastic Reel", Case Code (Imperial)=0805, Case Code (Metric)=2012, Manufacturer=Bourns, Manufacturer Part Number=CR0805-FX-1001ELF, Max Operating Temperature=155°C, Max Power Dissipation=125mW, Min Operating Temperature=-55°C, Package Quantity=1, Resistance=1kR, Resistance Tolerance=1%, Resistor Type="Thick Film", Supplier Part Number 1=CR0805-FX-1001ELFCT-ND, Temperature Coefficient=100ppm/°C, Voltage Rating=150V
R28 R29 R30: library part "R_3.3k SR0805FR-473K3L", "Res Thick Film 0805 3.3K Ohm 1% 0.5W(1/2W) ±100ppm/°C Pad SMD Automotive T/R", Manufacturer=Yageo, Manufacturer Part Number=SR0805FR-473K3L, Supplier Part Number 1=YAG5852CT-ND
R31 R32 R33: library part "R_100 SR0805JR-47100RL", "Res Thick Film 0805 100 Ohm 5% 0.5W(1/2W) ±100ppm/C Pad SMD Automotive T/R", Manufacturer=Yageo, Manufacturer Part Number=SR0805JR-47100RL, Supplier Part Number 1=YAG5873CT-ND
R34: library part "R_53.6k RT0805FRE0753K6L", "High Precision-High Stability Chip Resistor Thin Film 0805 53.6kOhm 1% Paper T/R", Case Code (Imperial)=0805, Case Code (Metric)=2012, Manufacturer=Yageo, Manufacturer Part Number=RT0805FRE0753K6L, Max Operating Temperature=125°C, Max Power Dissipation=125mW, Min Operating Temperature=-55°C, Package Quantity=5000, Resistance=53.6kR, Resistor Type="Thin Film", Supplier Part Number 1=13-RT0805FRE0753K6LCT-ND, Temperature Coefficient=50ppm/°C, Tolerance=1%, Voltage Rating=150V
R35: library part "R_113k CRCW0805113KFKEA", "Res Thick Film 0805 113K Ohm 1% 1/8W ±100ppm/°C Molded SMD SMD Paper T/R", Case Code (Imperial)=0805, Case Code (Metric)=2012, Manufacturer=Vishay, Manufacturer Part Number=CRCW0805113KFKEA, Max Operating Temperature=155°C, Max Power Dissipation=125mW, Min Operating Temperature=-55°C, Package Quantity=5000, Resistance=113kR, Resistance Tolerance=1%, Resistor Type="Thick Film", Supplier Part Number 1=541-113KCCT-ND, Temperature Coefficient=100ppm/°C, Voltage Rating=150V
R36: library part "R_88.7k RC0805FR-0788K7L", "Res Thick Film 0805 88.7K Ohm 1% 0.125W(1/8W) ±100ppm/C Pad SMD T/R", Case Code (Imperial)=0805, Case Code (Metric)=2012, Manufacturer=Yageo, Manufacturer Part Number=RC0805FR-0788K7L, Max Operating Temperature=155°C, Max Power Dissipation=125mW, Min Operating Temperature=-55°C, Package Quantity=1, Resistance=88.7kR, Resistor Type="Thick Film", Supplier Part Number 1=311-88.7KCRCT-ND, Temperature Coefficient=100ppm/°C, Tolerance=1%, Voltage Rating=150V
R38: library part "R_5.49k RC0805FR-075K49L", "Res Thick Film 2.0 x 1.2 mm 5.49K Ohm 1% 0.125W(1/8W) 100ppm/ C Molded SMD Paper T/R", Case Code (Imperial)=0805, Case Code (Metric)=2012, Manufacturer=Yageo, Manufacturer Part Number=RC0805FR-075K49L, Max Operating Temperature=155°C, Max Power Dissipation=125mW, Min Operating Temperature=-55°C, Package Quantity=1, Resistance=5.49kR, Resistor Type="Thick Film", Supplier Part Number 1=311-5.49KCRCT-ND, Temperature Coefficient=100ppm/°C, Tolerance=1%, Voltage Rating=150V
R39: library part "R_154k RC0805FR-07154KL", "Res Thick Film 2.0 x 1.2 mm 154K Ohm 1% 0.125W(1/8W) 100ppm/ C Molded SMD Paper T/R", Case Code (Imperial)=0805, Case Code (Metric)=2012, Manufacturer=Yageo, Manufacturer Part Number=RC0805FR-07154KL, Max Operating Temperature=155°C, Max Power Dissipation=125mW, Min Operating Temperature=-55°C, Package Quantity=1, Resistance=154kR, Resistor Type="Thick Film", Supplier Part Number 1=311-154KCRCT-ND, Temperature Coefficient=100ppm/°C, Tolerance=1%, Voltage Rating=150V
TP1 TP2 TP3 TP4 TP5 TP6 TP7 TP8 TP9 TP13 TP14 TP15 TP16 TP17 TP18 TP19 TP20 TP21 TP22 TP23 TP24 TP25 TP26 TP27 TP28 TP29 TP30: "Test Point, Round, Surface Pad"
U1: "No Description Available", Mfr_Name="Texas Instruments"
U2: "IC ADC 12BIT SAR 8SOIC", Mfr_Name=Microchip
U3: library part Hall_Sensor_DRV5011, "MAGNETIC SWITCH LATCH TO92-3"
U5: "IC USB SERIAL BASIC UART 12DFN", Mfr_Name="FTDI, Future Technology Devices International Ltd"
U6: "3.5V to 60V Input, 1.5A Step-Down Converter with Eco-Mode 10-HVSSOP -40 to 150", Case/Package="HTSSOP EP", Manufacturer="Texas Instruments", Max Input Voltage=60V, Max Operating Temperature=150°C, Max Output Current=1.5A, Max Output Voltage=58V, Min Input Voltage=3.5V, Min Operating Temperature=-40°C, Min Output Voltage=800mV, Package Quantity=80, Quiescent Current=116uA, Supplier Part Number 1=296-23864-5-ND, Switching Frequency=581kHz
U7: "Voltage Regulator with Enable 3.45V 150mA 1uA IQ 5-Pin SOT-23 T/R", Manufacturer="Texas Instruments", Supplier Part Number 1=296-TPS709B345DBVRCT-ND

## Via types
v1: diameter 0.6, hole 0.3, Top Layer to Bottom Layer, 669 vias
v2: diameter 5.08, hole 2.54, Top Layer to Bottom Layer, 6 vias
v3: diameter 1.5, hole 0.7, Top Layer to Bottom Layer, 1 vias
v4: diameter 4.7, hole 2, Top Layer to Bottom Layer, 1 vias

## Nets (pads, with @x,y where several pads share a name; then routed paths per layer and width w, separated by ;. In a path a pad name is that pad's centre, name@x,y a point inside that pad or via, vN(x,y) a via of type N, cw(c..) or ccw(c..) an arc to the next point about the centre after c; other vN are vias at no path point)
3V3: C31.1 C32.2 C34.1 C39.2 C47.2 D1.1 D2.1 D4.1 J3.5 R1.2 R10.2 R15.2 R17.1 R28.2 R29.2 R30.2 TP1.1 TP29.1 U2.8 U7.3 | length 414.8
  Top Layer w0.254: U2.8@129.818,22.259 U2.8@130.293,22.259 ; R1.2@145.906,23.271 146.088,23.453 TP1.1@151.539,23.453 151.441,23.355 151.441,20.237 v1(151.432,20.229)
  Top Layer w0.3: C32.2@173.704,27.945 173.758,27.999 C34.1@173.758,34.438
  Top Layer w0.4: D1.1@109.581,51.585 109.581,35.728 123.134,22.175 v1(127.964,22.175) 129.733,22.175 U2.8@129.818,22.259 ; C34.1@173.758,34.438 173.758,39.777 C31.1@173.948,39.968 177.079,39.968 v1(177.153,39.894)
  Top Layer w0.5: v1(37.935,138.573) 37.962,138.573 38.561,137.974 R29.2@41.086,137.974 ; v1(38.076,129.816) 39.493,129.816 40.857,128.452 R28.2@41.022,128.452 ; v1(38.118,116.589) 38.137,116.57 39.06,116.57 40.609,115.021 R30.2@40.774,115.021 ; TP29.1@69.949,77.329 69.963,77.342 77.39,77.342 C39.2@77.404,77.356 77.679,77.356 82.649,82.327 U7.3@85.749,82.327 85.749,80.077 85.685,80.013 v1(85.685,79.986) ; v1(106.605,51.543) 106.632,51.543 106.674,51.585 D1.1@109.581,51.585 D1.1@109.602,51.605 ; v1(106.983,61.37) 107.01,61.37 107.196,61.556 D2.1@109.622,61.556 D2.1@109.602,61.536 ; v1(110.007,73.943) 110.007,73.97 110.071,74.034 D4.1@110.071,76.463 ; R10.2@133.22,62.355 R10.2@133.22,62.33 ; R10.2@133.47,62.105 133.445,62.105 R10.2@133.22,62.33 ; R15.2@133.823,57.229 133.798,57.229 133.573,57.454 133.573,57.479 127.392,63.66 v1(127.392,67.72) ; R17.1@140.282,67.391 138.62,67.391 134.598,71.412 131.085,71.412 v1(127.392,67.72) ; v1(153.861,41.602) 153.88,41.621 153.88,41.791 158.167,46.078 C47.2@158.332,46.078 ; v1(127.392,67.72) 127.411,67.701 127.849,67.701 R10.2@133.22,62.33
  PWR w0.4: v1(127.964,22.175) 129.91,20.229 v1(151.432,20.229) v1@151.556,20.352 ; v1(153.861,41.602) 153.861,25.789 151.556,23.483 v1@151.556,20.352 ; v1(177.153,39.894) 157.611,20.352 v1@151.556,20.352
  PWR w0.5: J3.5@16.571,115.953 37.454,115.953 ; v1(37.935,138.573) 37.935,129.983 38.076,129.843 v1(38.076,129.816) 38.076,123.233 38.118,123.191 v1(38.118,116.589) 38.09,116.589 37.454,115.953 ; v1(106.605,51.543) 104.301,53.848 104.301,61.37 ; v1(106.983,61.37) 104.301,61.37 ; v1(127.392,67.72) 121.169,73.943 v1(110.007,73.943) 91.728,73.943 ; 37.454,115.953 49.718,115.953 v1(85.685,79.986) 91.728,73.943 ; 91.728,73.943 104.301,61.37
5V: C29.1 C41.2 J4.1 L1.2 R22.1 R34.2 R40.2 TP28.1 TP30.1 U7.2 | length 411.6
  Top Layer w0.5: TP30.1@17.11,92.665 20.778,92.665 ; v1(20.373,89.564) 20.373,92.261 20.778,92.665 ; L1.2@24.917,60.896 24.917,64.992 31.057,71.132 R34.2@31.057,71.297 30.879,71.475 30.879,82.486 R40.2@30.701,82.663 30.793,82.755 30.793,92.46 C41.2@30.885,92.552 ; C41.2@30.753,92.684 C41.2@30.772,92.665 ; TP28.1@70.022,85.813 70.029,85.82 77.2,85.82 C29.1@77.207,85.827 ; U7.2@85.749,83.277 79.923,83.277 77.372,85.827 C29.1@77.207,85.827 ; R22.1@180.245,45.039 182.836,45.039 183.333,45.536 v1(183.36,45.536) ; 20.778,92.665 C41.2@30.772,92.665 ; C41.2@30.772,92.665 C41.2@30.885,92.552 ; C41.2@30.885,92.552 30.885,92.717 35.259,97.092 65.778,97.092 77.042,85.827 C29.1@77.207,85.827
  PWR w0.5: v1(20.373,89.564) 8.961,78.152 8.961,35.321 40.49,3.792 142.009,3.792 180.387,42.171 180.387,42.563 v1(183.36,45.536) 195.593,45.536 J4.1@203.221,37.908
GAIN: R19.2 U4.30 | length 6
  Top Layer w0.254: R19.2@142.14,52.234 142.165,52.234 142.513,52.582 142.513,52.607 145.902,55.996 145.902,56.496 145.919,56.513 U4.30@146.075,56.513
